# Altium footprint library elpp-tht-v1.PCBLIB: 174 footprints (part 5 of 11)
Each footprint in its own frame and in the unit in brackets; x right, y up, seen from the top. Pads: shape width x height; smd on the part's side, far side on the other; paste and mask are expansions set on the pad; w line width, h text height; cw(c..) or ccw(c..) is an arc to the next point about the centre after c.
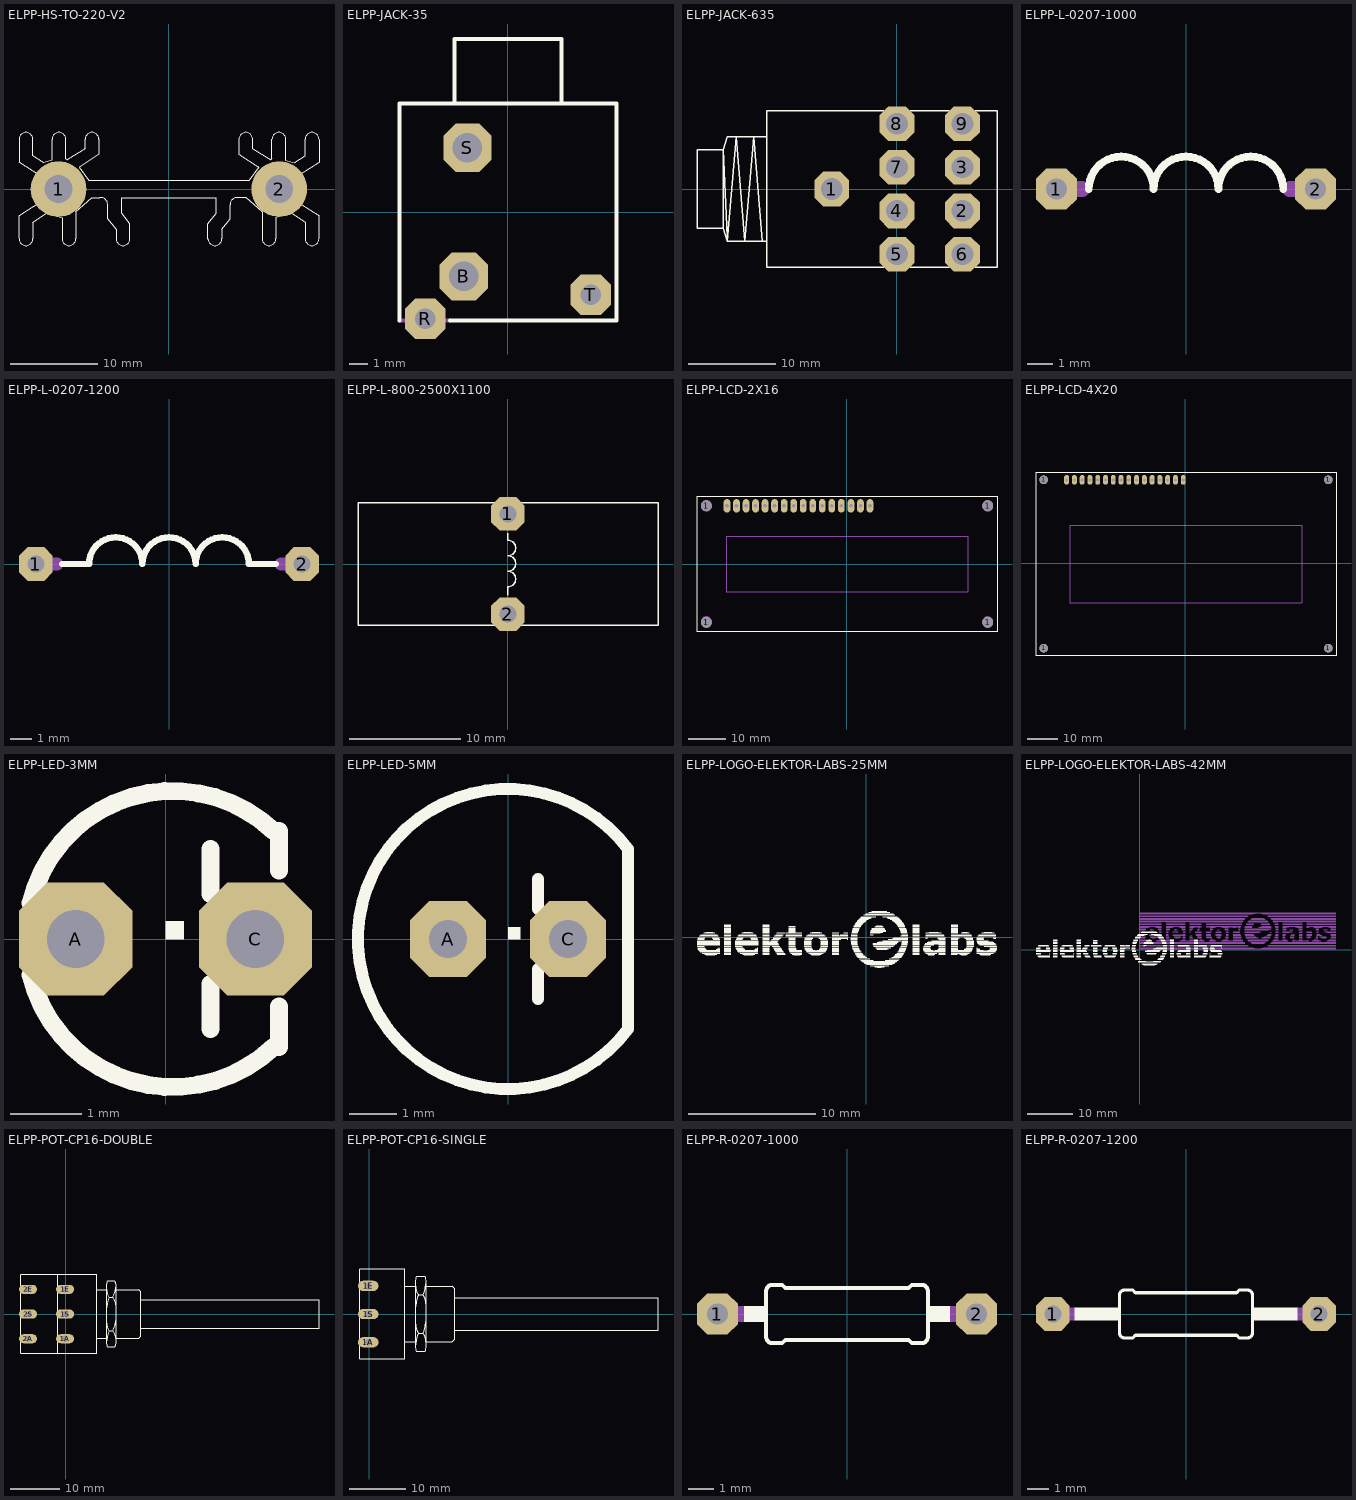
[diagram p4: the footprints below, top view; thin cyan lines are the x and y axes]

## ELPP-HS-TO-220-V2 [mil]
pads (2):
  round 252 hole 126: 1(-500,0) 2(500,0)
Top Overlay:
  lines w5: -679.13,-224.41 ccw(c-647.64,-224.41) -616.14,-224.41 -616.14,-149.61 -551.18,-106.3 -484.25,-129.92 -484.25,-224.41 ccw(c-452.76,-224.41) -421.26,-224.41 -421.26,-102.36 -350,-40 -314.17,-39.37 cw(c-308.54,-70.64) -276.77,-70.87 -276.77,-133.86 -239.37,-181.1 -239.37,-224.41 ccw(c-207.87,-224.41) -176.38,-224.41 ; -679.13,-222.44 -679.13,-120.08 -551.18,-39.37 ccw(c-499.59,0.32) -551.18,40 -679.13,121 -679.13,223 ; -679.13,225 cw(c-647.64,225) -616.14,225 -616.14,150 -566.93,119 -529.53,130 -529.53,225 cw(c-498.03,225) -466.54,225 -466.54,138 -460.63,132 -379.92,182 -379.92,225 cw(c-348.43,225) -316.93,225 ; -316.93,227 -316.93,225 ; -176.38,-226.38 -176.38,-224.41 ; 177,-226.38 177,-224.41 ; 317,227 317,225 ; 680,-224.41 cw(c648.5,-224.41) 617,-224.41 617,-149.61 552,-106.3 485,-129.92 485,-224.41 cw(c453.5,-224.41) 422,-224.41 422,-102.36 350,-40 315,-39.37 ccw(c309.07,-70.89) 277,-70.87 277,-133.86 240,-181.1 240,-224.41 cw(c208.5,-224.41) 177,-224.41 ; 680,-222.44 680,-120.08 552,-39.37 cw(c500.41,0.32) 552,40 680,121 680,223 ; 680,225 ccw(c648.5,225) 617,225 617,150 567,119 530,130 530,225 ccw(c498.5,225) 467,225 467,138 461,132 380,182 380,225 ccw(c348.5,225) 317,225 ; -316.93,225 -316.93,158 -405.51,99 -364.17,40 365,40 406,99 317,158 317,225 ; -176.38,-224.41 -176.38,-157.48 -213.78,-110.24 -213.78,-39.37 214,-39.37 214,-110.24 177,-157.48 177,-224.41
Mechanical 2:
  text ">NAME" at -200,-100 h42.5
Mechanical 4:
  text ">VALUE" at -300,50 h42.5

## ELPP-JACK-35 [mil]
pads (4):
  oct 103x103 hole 63: B(-94.49,-137.8) S(-86.61,138)
  oct 87x87 hole 44: R(-177.17,-228.35) T(178,-177.17)
Top Overlay:
  lines w8: -232.28,-232.28 -232.28,233 233,233 233,-232.28 -124.02,-232.28 ; -114.17,237 -114.17,371 115,371 115,237
Mechanical 2:
  text ">NAME" at -250,-225 h42.5
Mechanical 4:
  text ">VALUE" at 300,-225 h42.5
Mechanical 16:
  lines w8: -232.28,-232.28 -124.02,-232.28

## ELPP-JACK-635 [mil]
pads (9):
  oct 158x158 hole 99: 1(-295.28,0) 2(296,-98.43) 3(296,99) 4(0,-98.43) 5(0,-295.28) 6(296,-295.28) 7(0,99) 8(0,296) 9(296,296)
Top Overlay:
  lines w6: -767.72,-216.54 -787.4,178 ; -59.06,-354.33 -590.55,-354.33 -590.55,-236.22 ; -59.06,355 -590.55,355 -590.55,237 ; 60,-354.33 237,-354.33 ; 60,355 237,355 ; 355,-354.33 453,-354.33 453,355 355,355 ; -787.4,-177.17 -787.4,178 ; -787.4,-177.17 -905.51,-177.17 -905.51,178 -787.4,178 ; -787.4,-177.17 -767.72,-236.22 ; -787.4,178 -767.72,237 -728.35,237 ; -767.72,-236.22 -688.98,-236.22 ; -767.72,-236.22 -728.35,237 ; -728.35,237 -649.61,237 ; -728.35,237 -688.98,-236.22 ; -688.98,-236.22 -610.24,-236.22 ; -688.98,-236.22 -649.61,237 ; -649.61,237 -590.55,237 ; -649.61,237 -610.24,-236.22 ; -610.24,-236.22 -590.55,-236.22 ; -590.55,-236.22 -590.55,237
Mechanical 2:
  text ">NAME" at 200,400 h42.5
Mechanical 4:
  text ">VALUE" at -450,-300 h42.5

## ELPP-L-0207-1000 [mil]
pads (2):
  oct 63x63 hole 32: 1(-200,0) 2(200,0)
Top Overlay:
  lines w12: -150,0 cw(c-100,0) -100,50 cw(c-100,0) -50,0 cw(c0,0) 0,50 cw(c0,0) 50,0 cw(c100,0) 100,50 cw(c100,0) 150,0
Mechanical 2:
  text ">NAME" at -120,60 h42.5
Mechanical 4:
  text ">VALUE" at -139,-75 h42.5
Mechanical 16:
  lines w24: -200,0 -160,0 ; 160,0 200,0

## ELPP-L-0207-1200 [mil]
pads (2):
  oct 63x63 hole 32: 1(-250,0) 2(250,0)
Top Overlay:
  lines w12: -200,0 -150,0 cw(c-100,0) -100,50 cw(c-100,0) -50,0 cw(c0,0) 0,50 cw(c0,0) 50,0 cw(c100,0) 100,50 cw(c100,0) 150,0 200,0
Mechanical 2:
  text ">NAME" at -120,60 h42.5
Mechanical 4:
  text ">VALUE" at -139,-75 h42.5
Mechanical 16:
  lines w24: -250,0 -210,0 ; 210,0 250,0

## ELPP-L-800-2500X1100 [mil]
pads (2):
  oct 119x119 hole 60: 1(0,178) 2(0,-177.17)
Top Overlay:
  lines w5: 0,-110 0,-80 ccw(c0,-52.5) 0,-25 ccw(c0,2.5) 0,30 ccw(c0,57.5) 0,85 0,110 ; -531.5,-216.54 -531.5,217 532,217 532,-216.54 -531.5,-216.54
Mechanical 2:
  text ">NAME" at -511.81,237 h42.5
Mechanical 4:
  text ">VALUE" at -314.96,-39.37 h42.5

## ELPP-LCD-2X16 [mil]
pads (20):
  round 111 hole 111: 1(-1476.38,-610.24) 1(-1476.38,611) 1(1477,-610.24) 1(1477,611)
  oval 71x142 hole 40: 1(-1259.84,611) 2(-1159.84,611) 3(-1059.84,611) 4(-959.84,611) 5(-859.84,611) 6(-759.84,611) 7(-659.84,611) 8(-559.84,611) 9(-459.84,611) 10(-359.84,611) 11(-259.84,611) 12(-159.84,611) 13(-59.84,611) 14(41,611) 15(141,611) 16(241,611)
Top Overlay:
  lines w8: -1574.8,-708.66 1575,-708.66 1575,709 -1574.8,709 -1574.8,-708.66
Mechanical 2:
  text ">NAME" at -1550,750 h42.5
Mechanical 4:
  text ">VALUE" at -550,0 h42.5
Mechanical 16:
  circle w5: c-1476.38,611 r55
  circle w5: c1477,611 r55
  circle w5: c1477,-610.24 r55
  circle w5: c-1476.38,-610.24 r56
  lines w5: -1270.28,-291.9 1270,-291.9 1270,291 -1270.28,291 -1270.28,-4.5 -1270.28,-291.9
  text "1" at -1350,600 h62
  text "1" at -1350.59,600 h62

## ELPP-LCD-4X20 [mil]
pads (20):
  round 111 hole 111: 1(-1820.71,-1090.68) 1(-1820.71,1075) 1(1841,-1090.68) 1(1841,1075)
  oval 63x126 hole 40: 1(-1525.43,1075) 2(-1425.43,1075) 3(-1325.43,1075) 4(-1225.43,1075) 5(-1125.43,1075) 6(-1025.43,1075) 7(-925.43,1075) 8(-825.43,1075) 9(-725.43,1075) 10(-625.43,1075) 11(-525.43,1075) 12(-425.43,1075) 13(-325.43,1075) 14(-225.43,1075) 15(-125.43,1075) 16(-25.43,1075)
Top Overlay:
  lines w5: -1840.39,1174 1310,1174 ; -1919.13,-1189.1 -1919.13,1174 1507,1174 1940,1174 1940,-1189.1 1507,-1189.1 -1919.13,-1189.1
Mechanical 2:
  text ">NAME" at -1900,1200 h42.5
Mechanical 4:
  text ">VALUE" at -600,0 h42.5
Mechanical 16:
  lines w5: -1486.06,-504.06 1498,-504.06 1498,489 -1486.06,489 -1486.06,-504.06
  text "1" at -1615.59,1065 h62

## ELPP-LED-3MM [mil]
pads (2):
  oct 63x63 hole 32: A(-50,0) C(50,0)
Top Overlay:
  region: 0,0 10,0 10,10 0,10
  lines w10: -75,-20 ccw(c4.05,-1.03) 60,-60 ; -75,20 cw(c4.05,1.03) 60,60 ; 25,-50 25,-25 ; 25,25 25,50 ; 63,-60 63,-37.5 ; 63,38 63,60
Mechanical 2:
  text ">NAME" at 88,13 h42.5
Mechanical 4:
  text ">VALUE" at 88,-62.5 h42.5

## ELPP-LED-5MM [mil]
pads (2):
  oct 63x63 hole 32: A(-50,0) C(50,0)
Top Overlay:
  region: 0,0 10,0 10,10 0,10
  lines w10: 25,-50 25,-25 ; 25,25 25,50 ; 100,-75 100,75 ccw(c0,0) 100,-75
Mechanical 2:
  text ">NAME" at 125,25 h42.5
Mechanical 4:
  text ">VALUE" at 125,-62.5 h42.5

## ELPP-LOGO-ELEKTOR-LABS-25MM [mil]
Top Overlay:
  drawing of 1342 lines, arcs and shapes, not listed

## ELPP-LOGO-ELEKTOR-LABS-42MM [mil]
Top Overlay:
  drawing of 1342 lines, arcs and shapes, not listed
Mech68:
  drawing of 1508 lines, arcs and shapes, not listed
  text "C:/Elektor/Elektor Projects/dot labs logo bw.bmp" at 0,-10 h3.4

## ELPP-POT-CP16-DOUBLE [mil]
pads (6):
  oval 144x72 hole 48: 1A(-5.91,-196.85) 1E(-5.91,197) 1S(-5.91,0) 2A(-301.18,-196.85) 2E(-301.18,197) 2S(-301.18,0)
Top Overlay:
  lines w8: -49.21,-311.02 -360.24,-311.02 -360.24,312 -49.21,312 ; 325,-212.6 329,-181.1 337,-149.61 345,-133.86 ; 325,-55.12 329,-86.61 337,-118.11 345,-133.86 ; 325,56 329,87 337,119 345,134 ; 325,213 329,182 337,150 345,134 ; 396,-212.6 392,-181.1 384,-149.61 376,-133.86 ; 396,-55.12 392,-86.61 384,-118.11 376,-133.86 ; 396,56 392,87 384,119 376,134 ; 396,213 392,182 384,150 376,134 ; 601,-114.17 2018,-114.17 2018,115 601,115 ; 247,-192.91 247,-311.02 -64.96,-311.02 -64.96,312 247,312 247,193 ; 247,-192.91 247,193 ; 247,-192.91 325,-192.91 ; 247,193 325,193 ; 325,-192.91 325,-224.41 329,-251.97 333,-263.78 388,-263.78 392,-251.97 396,-224.41 396,-192.91 ; 325,-192.91 325,193 ; 325,193 325,225 329,252 333,264 388,264 392,252 396,225 396,193 ; 345,-133.86 376,-133.86 ; 345,134 376,134 ; 396,-192.91 581,-192.91 597,-177.17 597,178 581,193 396,193 ; 396,-192.91 396,193
Mechanical 2:
  text ">NAME" at 230,-327.56 h42.5
Mechanical 4:
  text ">VALUE" at 230,390 h42.5

## ELPP-POT-CP16-SINGLE [mil]
pads (3):
  oval 144x72 hole 48: 1A(-5.91,-196.85) 1E(-5.91,197) 1S(-5.91,0)
Top Overlay:
  lines w8: 325,-212.6 329,-181.1 337,-149.61 345,-133.86 ; 325,-55.12 329,-86.61 337,-118.11 345,-133.86 ; 325,56 329,87 337,119 345,134 ; 325,213 329,182 337,150 345,134 ; 376,-134.14 384,-118.39 ; 384,-118.11 392,-86.61 396,-55.12 ; 396,-212.6 392,-181.1 384,-149.61 376,-133.86 345,-133.86 ; 396,56 392,87 384,119 376,134 ; 396,213 392,182 384,150 376,134 ; 601,-114.17 2018,-114.17 2018,115 601,115 ; 247,-192.91 247,-311.02 -64.96,-311.02 -64.96,312 247,312 247,193 ; 247,-192.91 247,193 ; 247,-192.91 325,-192.91 ; 247,193 325,193 ; 325,-192.91 325,-224.41 329,-251.97 333,-263.78 388,-263.78 392,-251.97 396,-224.41 396,-192.91 ; 325,-192.91 325,193 ; 325,193 325,225 329,252 333,264 388,264 392,252 396,225 396,193 ; 345,134 376,134 ; 396,-192.91 581,-192.91 597,-177.17 597,178 581,193 396,193 ; 396,-192.91 396,193
Mechanical 2:
  text ">NAME" at 230,-327.56 h42.5
Mechanical 4:
  text ">VALUE" at 230,390 h42.5

## ELPP-R-0207-1000 [mil]
pads (2):
  oct 63x63 hole 32: 1(-200,0) 2(200,0)
Top Overlay:
  rectangle: 125,-12 159,12
  rectangle: -159,-12 -125,12
  lines w6: -125,-35 ccw(c-115,-35) -115,-45 -100,-45 -95,-40 95,-40 100,-45 115,-45 ccw(c115,-35) 125,-35 125,35 ccw(c115,35) 115,45 100,45 95,40 -95,40 -100,45 -115,45 ccw(c-115,35) -125,35 -125,-35
Mechanical 2:
  text ">NAME" at -120,60 h42.5
Mechanical 4:
  text ">VALUE" at -89,-25 h42.5
Mechanical 16:
  lines w24: -200,0 -160,0 ; 160,0 200,0

## ELPP-R-0207-1200 [mil]
pads (2):
  oct 63x63 hole 32: 1(-250,0) 2(250,0)
Top Overlay:
  rectangle: 125,-12 159,12
  rectangle: -159,-12 -125,12
  rectangle: 175,-12 209,12
  rectangle: -209,-12 -175,12
  lines w6: -125,-35 ccw(c-115,-35) -115,-45 -100,-45 -95,-40 95,-40 100,-45 115,-45 ccw(c115,-35) 125,-35 125,35 ccw(c115,35) 115,45 100,45 95,40 -95,40 -100,45 -115,45 ccw(c-115,35) -125,35 -125,-35
  lines w24: -175,0 -160,0 ; 160,0 175,0
Mechanical 2:
  text ">NAME" at -125,55 h42.5
Mechanical 4:
  text ">VALUE" at -90,-27 h42.5
Mechanical 16:
  lines w24: -250,0 -210,0 ; 210,0 250,0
